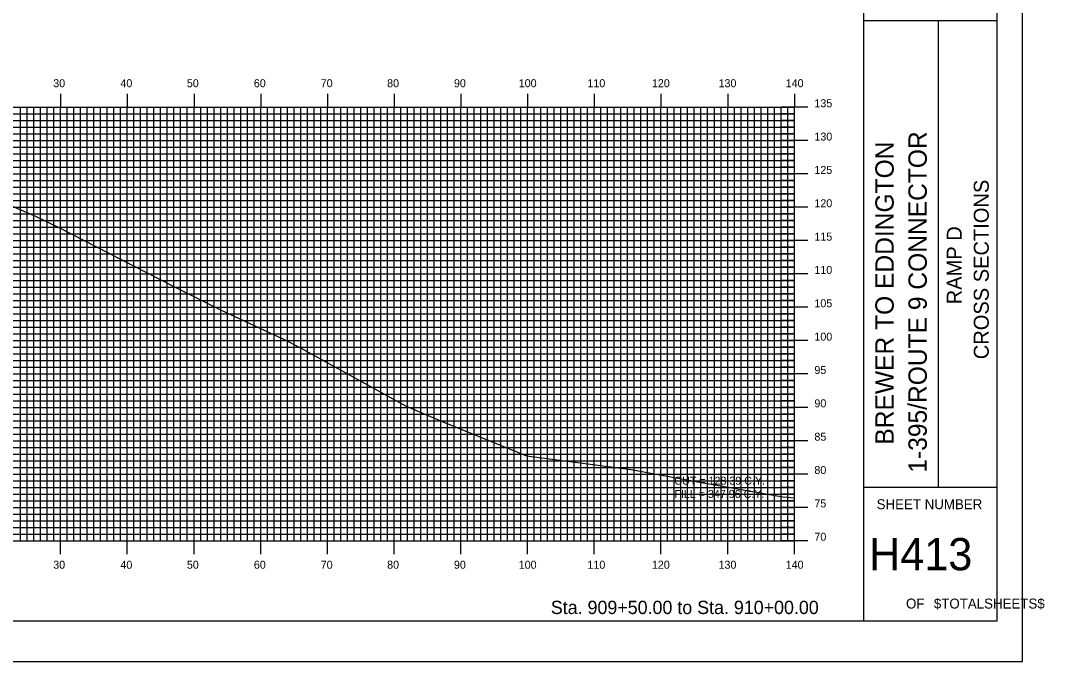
# Model space of a CAD drawing. Extents: x 859078 to 859421, y 364765 to 364985.
# Drawn here: x 859267.3 to 859420.9, y 364765.2 to 364861.3 of the extents above; entities that cross this region are included whole.
import ezdxf

# ---------------------------------------------------------------- set-up
doc = ezdxf.new("R2010")
doc.units = 0
for name, color, linetype in [('BORDER', 7, 'Continuous'), ('D_Text_Standard', 7, 'Continuous'), ('H_V ANNOTATION', 7, 'Continuous'), ('MAJOR', 7, 'Continuous'), ('MINOR', 7, 'Continuous'), ('PLOT BOUNDARY', 7, 'Continuous'), ('S_Roadway_Centerline', 7, 'Continuous')]:
    doc.layers.add(name, color=color, linetype=linetype)

msp = doc.modelspace()

# ---------------------------------------------------------------- linework, layer by layer
at = {"layer": 'BORDER'}
for p, q in [((859393.76, 364771.3), (859393.76, 364981.3)), ((859393.76, 364861.31), (859413.76, 364861.31)), ((859404.94, 364791.31), (859404.94, 364861.31)), ((859393.76, 364791.31), (859413.76, 364791.31))]:
    msp.add_line(p, q, dxfattribs=at)
msp.add_lwpolyline([(859093.76, 364771.3), (859413.76, 364771.3), (859413.76, 364981.3), (859093.76, 364981.3)], close=True, dxfattribs=at)
at = {"layer": 'MAJOR'}
for p, q in [((859273.36, 364850.31), (859273.36, 364848.3)), ((859283.36, 364850.31), (859283.36, 364848.3)), ((859293.36, 364850.31), (859293.36, 364848.3)), ((859303.36, 364850.31), (859303.36, 364848.3)), ((859313.36, 364850.31), (859313.36, 364848.3)), ((859323.36, 364850.31), (859323.36, 364848.3)), ((859333.36, 364850.31), (859333.36, 364848.3)), ((859343.36, 364850.31), (859343.36, 364848.3)), ((859353.36, 364850.31), (859353.36, 364848.3)), ((859363.36, 364850.31), (859363.36, 364848.3)), ((859373.36, 364850.31), (859373.36, 364848.3)), ((859383.36, 364850.31), (859383.36, 364848.3)), ((859103.36, 364848.3), (859383.36, 364848.3)), ((859103.36, 364848.3), (859383.36, 364848.3)), ((859273.36, 364783.3), (859273.36, 364848.3)), ((859283.36, 364783.3), (859283.36, 364848.3)), ((859293.36, 364783.3), (859293.36, 364848.3)), ((859303.36, 364783.3), (859303.36, 364848.3)), ((859313.36, 364783.3), (859313.36, 364848.3)), ((859323.36, 364783.3), (859323.36, 364848.3)), ((859333.36, 364783.3), (859333.36, 364848.3)), ((859343.36, 364783.3), (859343.36, 364848.3)), ((859353.36, 364783.3), (859353.36, 364848.3)), ((859363.36, 364783.3), (859363.36, 364848.3)), ((859373.36, 364783.3), (859373.36, 364848.3)), ((859385.36, 364848.3), (859381.36, 364848.3)), ((859383.36, 364783.3), (859383.36, 364848.3)), ((859383.36, 364783.3), (859383.36, 364848.3)), ((859103.36, 364843.3), (859383.36, 364843.3)), ((859385.36, 364843.3), (859381.36, 364843.3)), ((859103.36, 364838.3), (859383.36, 364838.3)), ((859385.36, 364838.3), (859381.36, 364838.3)), ((859103.36, 364833.3), (859383.36, 364833.3)), ((859385.36, 364833.3), (859381.36, 364833.3)), ((859103.36, 364828.3), (859383.36, 364828.3)), ((859385.36, 364828.3), (859381.36, 364828.3)), ((859103.36, 364823.3), (859383.36, 364823.3)), ((859385.36, 364823.3), (859381.36, 364823.3)), ((859103.36, 364818.3), (859383.36, 364818.3)), ((859385.36, 364818.3), (859381.36, 364818.3)), ((859103.36, 364813.3), (859383.36, 364813.3)), ((859385.36, 364813.3), (859381.36, 364813.3)), ((859103.36, 364808.3), (859383.36, 364808.3)), ((859385.36, 364808.3), (859381.36, 364808.3)), ((859103.36, 364803.3), (859383.36, 364803.3)), ((859385.36, 364803.3), (859381.36, 364803.3)), ((859103.36, 364798.3), (859383.36, 364798.3)), ((859385.36, 364798.3), (859381.36, 364798.3)), ((859103.36, 364793.3), (859383.36, 364793.3)), ((859385.36, 364793.3), (859381.36, 364793.3)), ((859103.36, 364788.3), (859383.36, 364788.3)), ((859385.36, 364788.3), (859381.36, 364788.3)), ((859103.36, 364783.3), (859383.36, 364783.3)), ((859103.36, 364783.3), (859383.36, 364783.3)), ((859273.36, 364781.3), (859273.36, 364783.3)), ((859283.36, 364781.3), (859283.36, 364783.3)), ((859293.36, 364781.3), (859293.36, 364783.3)), ((859303.36, 364781.3), (859303.36, 364783.3)), ((859313.36, 364781.3), (859313.36, 364783.3)), ((859323.36, 364781.3), (859323.36, 364783.3)), ((859333.36, 364781.3), (859333.36, 364783.3)), ((859343.36, 364781.3), (859343.36, 364783.3)), ((859353.36, 364781.3), (859353.36, 364783.3)), ((859363.36, 364781.3), (859363.36, 364783.3)), ((859373.36, 364781.3), (859373.36, 364783.3)), ((859385.36, 364783.3), (859381.36, 364783.3)), ((859383.36, 364781.3), (859383.36, 364783.3))]:
    msp.add_line(p, q, dxfattribs=at)
at = {"layer": 'MINOR'}
for p, q in [((859267.36, 364783.3), (859267.36, 364848.3)), ((859268.36, 364783.3), (859268.36, 364848.3)), ((859269.36, 364783.3), (859269.36, 364848.3)), ((859270.36, 364783.3), (859270.36, 364848.3)), ((859271.36, 364783.3), (859271.36, 364848.3)), ((859272.36, 364783.3), (859272.36, 364848.3)), ((859274.36, 364783.3), (859274.36, 364848.3)), ((859275.36, 364783.3), (859275.36, 364848.3)), ((859276.36, 364783.3), (859276.36, 364848.3)), ((859277.36, 364783.3), (859277.36, 364848.3)), ((859278.36, 364783.3), (859278.36, 364848.3)), ((859279.36, 364783.3), (859279.36, 364848.3)), ((859280.36, 364783.3), (859280.36, 364848.3)), ((859281.36, 364783.3), (859281.36, 364848.3)), ((859282.36, 364783.3), (859282.36, 364848.3)), ((859284.36, 364783.3), (859284.36, 364848.3)), ((859285.36, 364783.3), (859285.36, 364848.3)), ((859286.36, 364783.3), (859286.36, 364848.3)), ((859287.36, 364783.3), (859287.36, 364848.3)), ((859288.36, 364783.3), (859288.36, 364848.3)), ((859289.36, 364783.3), (859289.36, 364848.3)), ((859290.36, 364783.3), (859290.36, 364848.3)), ((859291.36, 364783.3), (859291.36, 364848.3)), ((859292.36, 364783.3), (859292.36, 364848.3)), ((859294.36, 364783.3), (859294.36, 364848.3)), ((859295.36, 364783.3), (859295.36, 364848.3)), ((859296.36, 364783.3), (859296.36, 364848.3)), ((859297.36, 364783.3), (859297.36, 364848.3)), ((859298.36, 364783.3), (859298.36, 364848.3)), ((859299.36, 364783.3), (859299.36, 364848.3)), ((859300.36, 364783.3), (859300.36, 364848.3)), ((859301.36, 364783.3), (859301.36, 364848.3)), ((859302.36, 364783.3), (859302.36, 364848.3)), ((859304.36, 364783.3), (859304.36, 364848.3)), ((859305.36, 364783.3), (859305.36, 364848.3)), ((859306.36, 364783.3), (859306.36, 364848.3)), ((859307.36, 364783.3), (859307.36, 364848.3)), ((859308.36, 364783.3), (859308.36, 364848.3)), ((859309.36, 364783.3), (859309.36, 364848.3)), ((859310.36, 364783.3), (859310.36, 364848.3)), ((859311.36, 364783.3), (859311.36, 364848.3)), ((859312.36, 364783.3), (859312.36, 364848.3)), ((859314.36, 364783.3), (859314.36, 364848.3)), ((859315.36, 364783.3), (859315.36, 364848.3)), ((859316.36, 364783.3), (859316.36, 364848.3)), ((859317.36, 364783.3), (859317.36, 364848.3)), ((859318.36, 364783.3), (859318.36, 364848.3)), ((859319.36, 364783.3), (859319.36, 364848.3)), ((859320.36, 364783.3), (859320.36, 364848.3)), ((859321.36, 364783.3), (859321.36, 364848.3)), ((859322.36, 364783.3), (859322.36, 364848.3)), ((859324.36, 364783.3), (859324.36, 364848.3)), ((859325.36, 364783.3), (859325.36, 364848.3)), ((859326.36, 364783.3), (859326.36, 364848.3)), ((859327.36, 364783.3), (859327.36, 364848.3)), ((859328.36, 364783.3), (859328.36, 364848.3)), ((859329.36, 364783.3), (859329.36, 364848.3)), ((859330.36, 364783.3), (859330.36, 364848.3)), ((859331.36, 364783.3), (859331.36, 364848.3)), ((859332.36, 364783.3), (859332.36, 364848.3)), ((859334.36, 364783.3), (859334.36, 364848.3)), ((859335.36, 364783.3), (859335.36, 364848.3)), ((859336.36, 364783.3), (859336.36, 364848.3)), ((859337.36, 364783.3), (859337.36, 364848.3)), ((859338.36, 364783.3), (859338.36, 364848.3)), ((859339.36, 364783.3), (859339.36, 364848.3)), ((859340.36, 364783.3), (859340.36, 364848.3)), ((859341.36, 364783.3), (859341.36, 364848.3)), ((859342.36, 364783.3), (859342.36, 364848.3)), ((859344.36, 364783.3), (859344.36, 364848.3)), ((859345.36, 364783.3), (859345.36, 364848.3)), ((859346.36, 364783.3), (859346.36, 364848.3)), ((859347.36, 364783.3), (859347.36, 364848.3)), ((859348.36, 364783.3), (859348.36, 364848.3)), ((859349.36, 364783.3), (859349.36, 364848.3)), ((859350.36, 364783.3), (859350.36, 364848.3)), ((859351.36, 364783.3), (859351.36, 364848.3)), ((859352.36, 364783.3), (859352.36, 364848.3)), ((859354.36, 364783.3), (859354.36, 364848.3)), ((859355.36, 364783.3), (859355.36, 364848.3)), ((859356.36, 364783.3), (859356.36, 364848.3)), ((859357.36, 364783.3), (859357.36, 364848.3)), ((859358.36, 364783.3), (859358.36, 364848.3)), ((859359.36, 364783.3), (859359.36, 364848.3)), ((859360.36, 364783.3), (859360.36, 364848.3)), ((859361.36, 364783.3), (859361.36, 364848.3)), ((859362.36, 364783.3), (859362.36, 364848.3)), ((859364.36, 364783.3), (859364.36, 364848.3)), ((859365.36, 364783.3), (859365.36, 364848.3)), ((859366.36, 364783.3), (859366.36, 364848.3)), ((859367.36, 364783.3), (859367.36, 364848.3)), ((859368.36, 364783.3), (859368.36, 364848.3)), ((859369.36, 364783.3), (859369.36, 364848.3)), ((859370.36, 364783.3), (859370.36, 364848.3)), ((859371.36, 364783.3), (859371.36, 364848.3)), ((859372.36, 364783.3), (859372.36, 364848.3)), ((859374.36, 364783.3), (859374.36, 364848.3)), ((859375.36, 364783.3), (859375.36, 364848.3)), ((859376.36, 364783.3), (859376.36, 364848.3)), ((859377.36, 364783.3), (859377.36, 364848.3)), ((859378.36, 364783.3), (859378.36, 364848.3)), ((859379.36, 364783.3), (859379.36, 364848.3)), ((859380.36, 364783.3), (859380.36, 364848.3)), ((859381.36, 364783.3), (859381.36, 364848.3)), ((859382.36, 364783.3), (859382.36, 364848.3)), ((859103.36, 364847.3), (859383.36, 364847.3)), ((859103.36, 364846.3), (859383.36, 364846.3)), ((859383.36, 364847.3), (859381.36, 364847.3)), ((859383.36, 364846.3), (859381.36, 364846.3)), ((859103.36, 364845.3), (859383.36, 364845.3)), ((859383.36, 364845.3), (859381.36, 364845.3)), ((859103.36, 364844.3), (859383.36, 364844.3)), ((859383.36, 364844.3), (859381.36, 364844.3)), ((859103.36, 364842.3), (859383.36, 364842.3)), ((859103.36, 364841.3), (859383.36, 364841.3)), ((859383.36, 364842.3), (859381.36, 364842.3)), ((859383.36, 364841.3), (859381.36, 364841.3)), ((859103.36, 364840.3), (859383.36, 364840.3)), ((859383.36, 364840.3), (859381.36, 364840.3)), ((859103.36, 364839.3), (859383.36, 364839.3)), ((859383.36, 364839.3), (859381.36, 364839.3)), ((859103.36, 364837.3), (859383.36, 364837.3)), ((859383.36, 364837.3), (859381.36, 364837.3)), ((859103.36, 364836.3), (859383.36, 364836.3)), ((859103.36, 364835.3), (859383.36, 364835.3)), ((859383.36, 364836.3), (859381.36, 364836.3)), ((859383.36, 364835.3), (859381.36, 364835.3)), ((859103.36, 364834.3), (859383.36, 364834.3)), ((859383.36, 364834.3), (859381.36, 364834.3)), ((859103.36, 364832.3), (859383.36, 364832.3)), ((859383.36, 364832.3), (859381.36, 364832.3)), ((859103.36, 364831.3), (859383.36, 364831.3)), ((859383.36, 364831.3), (859381.36, 364831.3)), ((859103.36, 364830.3), (859383.36, 364830.3)), ((859103.36, 364829.3), (859383.36, 364829.3)), ((859383.36, 364830.3), (859381.36, 364830.3)), ((859383.36, 364829.3), (859381.36, 364829.3)), ((859103.36, 364827.3), (859383.36, 364827.3)), ((859103.36, 364826.3), (859383.36, 364826.3)), ((859383.36, 364827.3), (859381.36, 364827.3)), ((859383.36, 364826.3), (859381.36, 364826.3)), ((859103.36, 364825.3), (859383.36, 364825.3)), ((859383.36, 364825.3), (859381.36, 364825.3)), ((859103.36, 364824.3), (859383.36, 364824.3)), ((859383.36, 364824.3), (859381.36, 364824.3)), ((859103.36, 364822.3), (859383.36, 364822.3)), ((859103.36, 364821.3), (859383.36, 364821.3)), ((859383.36, 364822.3), (859381.36, 364822.3)), ((859383.36, 364821.3), (859381.36, 364821.3)), ((859103.36, 364820.3), (859383.36, 364820.3)), ((859383.36, 364820.3), (859381.36, 364820.3)), ((859103.36, 364819.3), (859383.36, 364819.3)), ((859383.36, 364819.3), (859381.36, 364819.3)), ((859103.36, 364817.3), (859383.36, 364817.3)), ((859383.36, 364817.3), (859381.36, 364817.3)), ((859103.36, 364816.3), (859383.36, 364816.3)), ((859103.36, 364815.3), (859383.36, 364815.3)), ((859383.36, 364816.3), (859381.36, 364816.3)), ((859383.36, 364815.3), (859381.36, 364815.3)), ((859103.36, 364814.3), (859383.36, 364814.3)), ((859383.36, 364814.3), (859381.36, 364814.3)), ((859103.36, 364812.3), (859383.36, 364812.3)), ((859383.36, 364812.3), (859381.36, 364812.3)), ((859103.36, 364811.3), (859383.36, 364811.3)), ((859383.36, 364811.3), (859381.36, 364811.3)), ((859103.36, 364810.3), (859383.36, 364810.3)), ((859103.36, 364809.3), (859383.36, 364809.3)), ((859383.36, 364810.3), (859381.36, 364810.3)), ((859383.36, 364809.3), (859381.36, 364809.3)), ((859103.36, 364807.3), (859383.36, 364807.3)), ((859103.36, 364806.3), (859383.36, 364806.3)), ((859383.36, 364807.3), (859381.36, 364807.3)), ((859383.36, 364806.3), (859381.36, 364806.3)), ((859103.36, 364805.3), (859383.36, 364805.3)), ((859383.36, 364805.3), (859381.36, 364805.3)), ((859103.36, 364804.3), (859383.36, 364804.3)), ((859383.36, 364804.3), (859381.36, 364804.3)), ((859103.36, 364802.3), (859383.36, 364802.3)), ((859383.36, 364802.3), (859381.36, 364802.3)), ((859103.36, 364801.3), (859383.36, 364801.3)), ((859103.36, 364800.3), (859383.36, 364800.3)), ((859383.36, 364801.3), (859381.36, 364801.3)), ((859383.36, 364800.3), (859381.36, 364800.3)), ((859103.36, 364799.3), (859383.36, 364799.3)), ((859383.36, 364799.3), (859381.36, 364799.3)), ((859103.36, 364797.3), (859383.36, 364797.3)), ((859383.36, 364797.3), (859381.36, 364797.3)), ((859103.36, 364796.3), (859383.36, 364796.3)), ((859103.36, 364795.3), (859383.36, 364795.3)), ((859383.36, 364796.3), (859381.36, 364796.3)), ((859383.36, 364795.3), (859381.36, 364795.3)), ((859103.36, 364794.3), (859383.36, 364794.3)), ((859383.36, 364794.3), (859381.36, 364794.3)), ((859103.36, 364792.3), (859383.36, 364792.3)), ((859383.36, 364792.3), (859381.36, 364792.3)), ((859103.36, 364791.3), (859383.36, 364791.3)), ((859383.36, 364791.3), (859381.36, 364791.3)), ((859103.36, 364790.3), (859383.36, 364790.3)), ((859103.36, 364789.3), (859383.36, 364789.3)), ((859383.36, 364790.3), (859381.36, 364790.3)), ((859383.36, 364789.3), (859381.36, 364789.3)), ((859103.36, 364787.3), (859383.36, 364787.3)), ((859103.36, 364786.3), (859383.36, 364786.3)), ((859383.36, 364787.3), (859381.36, 364787.3)), ((859383.36, 364786.3), (859381.36, 364786.3)), ((859103.36, 364785.3), (859383.36, 364785.3)), ((859383.36, 364785.3), (859381.36, 364785.3)), ((859103.36, 364784.3), (859383.36, 364784.3)), ((859383.36, 364784.3), (859381.36, 364784.3))]:
    msp.add_line(p, q, dxfattribs=at)
at = {"layer": 'PLOT BOUNDARY'}
msp.add_lwpolyline([(859077.57, 364765.18), (859417.57, 364765.18), (859417.57, 364985.18), (859077.57, 364985.18)], close=True, dxfattribs=at)
at = {"layer": 'S_Roadway_Centerline'}
msp.add_lwpolyline([(859248.58, 364840.97), (859269.62, 364831.98), (859273.11, 364830.28), (859290.05, 364821.55), (859297.34, 364817.93), (859306.76, 364813.53), (859309.31, 364812.22), (859310.12, 364811.77), (859325.16, 364803.5), (859330.81, 364801.1), (859343.19, 364796.03), (859358.89, 364794), (859368.89, 364792.13), (859381.62, 364789.87), (859383.36, 364789.72)], dxfattribs=at)

# ---------------------------------------------------------------- texts
at = {"layer": 'BORDER'}
for s, height, p in [('1-395/ROUTE 9 CONNECTOR', 2.7557, (859403.21, 364793.5)), ('BREWER TO EDDINGTON', 2.7557, (859398.25, 364797.71)), ('CROSS SECTIONS', 2.25, (859412.5, 364810.52)), ('RAMP D', 2.25, (859408.45, 364818.75))]:
    msp.add_text(s, height=height, rotation=90, dxfattribs=at).set_placement(p)
for s, height, p in [('SHEET NUMBER', 1.4905, (859395.69, 364788.03)), ('H413', 4.839, (859394.56, 364778.87)), ('OF', 1.491, (859400.09, 364773.13)), ('$TOTALSHEETS$', 1.4905, (859404.27, 364773.13))]:
    msp.add_text(s, height=height, dxfattribs=at).set_placement(p)
at = {"layer": 'D_Text_Standard'}
for s, p in [('CUT = 128.39 C.Y.', (859365.36, 364791.7)), ('FILL = 347.96 C.Y.', (859365.36, 364789.71))]:
    msp.add_text(s, height=1.2, dxfattribs=at).set_placement(p)
at = {"layer": 'H_V ANNOTATION'}
for s, height, p in [('30', 1.2, (859272.26, 364851.3)), ('40', 1.2, (859282.33, 364851.3)), ('50', 1.2, (859292.29, 364851.3)), ('60', 1.2, (859302.33, 364851.3)), ('70', 1.2, (859312.36, 364851.3)), ('80', 1.2, (859322.31, 364851.3)), ('90', 1.2, (859332.33, 364851.3)), ('100', 1.2, (859342.04, 364851.3)), ('110', 1.2, (859352.34, 364851.3)), ('120', 1.2, (859362, 364851.3)), ('130', 1.2, (859371.99, 364851.3)), ('140', 1.2, (859382.06, 364851.3)), ('135', 1.2, (859386.36, 364848.3)), ('130', 1.2, (859386.36, 364843.3)), ('125', 1.2, (859386.36, 364838.3)), ('120', 1.2, (859386.36, 364833.3)), ('115', 1.2, (859386.36, 364828.3)), ('110', 1.2, (859386.36, 364823.3)), ('105', 1.2, (859386.36, 364818.3)), ('100', 1.2, (859386.36, 364813.3)), ('95', 1.2, (859386.36, 364808.3)), ('90', 1.2, (859386.36, 364803.3)), ('85', 1.2, (859386.36, 364798.3)), ('80', 1.2, (859386.36, 364793.3)), ('75', 1.2, (859386.36, 364788.3)), ('70', 1.2, (859386.36, 364783.3)), ('30', 1.2, (859272.26, 364779.1)), ('40', 1.2, (859282.33, 364779.1)), ('50', 1.2, (859292.29, 364779.1)), ('60', 1.2, (859302.33, 364779.1)), ('70', 1.2, (859312.36, 364779.1)), ('80', 1.2, (859322.31, 364779.1)), ('90', 1.2, (859332.33, 364779.1)), ('100', 1.2, (859342.04, 364779.1)), ('110', 1.2, (859352.34, 364779.1)), ('120', 1.2, (859362, 364779.1)), ('130', 1.2, (859371.99, 364779.1)), ('140', 1.2, (859382.06, 364779.1)), ('Sta. 909+50.00 to Sta. 910+00.00', 2.0004, (859346.85, 364772.3))]:
    msp.add_text(s, height=height, dxfattribs=at).set_placement(p)

doc.saveas('drawing.dxf')
